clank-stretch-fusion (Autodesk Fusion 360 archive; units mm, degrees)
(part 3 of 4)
sketch "Profile" plane through (0, 0, 0) normal (1, 0, 0) x axis (0, 1, 0)
  line L1 (20, -33) -> (-20, -33)
  line L2 (20, 27) -> (20, -33)
  line L3 (-20, 27) -> (20, 27)
  line L4 (-20, -33) -> (-20, 27)
  line L5 (-55, -61.5) -> (-55, -1.5)
  line L6 (120, -61.5) -> (-55, -61.5)
  line L7 (120, -1.5) -> (120, -61.5)
  line L8 (20, -33) -> (-20, 27)
  line L9 (120, -1.5) -> (-55, -1.5)
  line L10 (106.0415, 5) -> (104.0207, 1.5)
  line L11 (104.0207, 8.5) -> (106.0415, 5)
  line L12 (99.9793, 8.5) -> (104.0207, 8.5)
  line L13 (97.9585, 5) -> (99.9793, 8.5)
  line L14 (99.9793, 1.5) -> (97.9585, 5)
  line L15 (104.0207, 1.5) -> (99.9793, 1.5)
  line L16 (97.9585, -67.85) -> (99.9793, -64.35)
  line L17 (104.0207, -71.35) -> (99.9793, -71.35)
  line L18 (106.0415, -67.85) -> (104.0207, -71.35)
  line L19 (99.9793, -71.35) -> (97.9585, -67.85)
  line L20 (104.0207, -64.35) -> (106.0415, -67.85)
  line L21 (99.9793, -64.35) -> (104.0207, -64.35)
  line L22 (-39.0415, 5) -> (-37.0207, 8.5)
  line L23 (-32.9793, 1.5) -> (-37.0207, 1.5)
  line L24 (-30.9585, 5) -> (-32.9793, 1.5)
  line L25 (-37.0207, 1.5) -> (-39.0415, 5)
  line L26 (-32.9793, 8.5) -> (-30.9585, 5)
  line L27 (-37.0207, 8.5) -> (-32.9793, 8.5)
  line L28 (-39.0415, -67.85) -> (-37.0207, -64.35)
  line L29 (-32.9793, -71.35) -> (-37.0207, -71.35)
  line L30 (-30.9585, -67.85) -> (-32.9793, -71.35)
  line L31 (-37.0207, -71.35) -> (-39.0415, -67.85)
  line L32 (-32.9793, -64.35) -> (-30.9585, -67.85)
  line L33 (-37.0207, -64.35) -> (-32.9793, -64.35)
  line L34 (-35, -67.85) -> (-35, 5)
  line L35 (102, -67.85) -> (102, 5)
  line L36 (10, 17) -> (-10, 17)
  line L37 (10, -23) -> (10, 17)
  line L38 (-10, -23) -> (10, -23)
  line L39 (-10, 17) -> (-10, -23)
  line L40 (10, 17) -> (-10, -23)
  line L41 (-23.9585, -58.31) -> (-28.9585, -58.31)
  line L42 (-23.9585, -72.31) -> (-23.9585, -58.31)
  line L43 (-28.9585, -72.31) -> (-23.9585, -72.31)
  line L44 (-28.9585, -58.31) -> (-28.9585, -72.31)
  line L45 (-42, -55.77) -> (-42, -74.85)
  line L46 (-23.9585, -55.77) -> (-42, -55.77)
  line L47 (-23.9585, -54.77) -> (-23.9585, -55.77)
  line L48 (-42, -54.77) -> (-23.9585, -54.77)
  line L49 (-42, 12) -> (-42, -54.77)
  line L50 (109, -74.85) -> (-42, -74.85)
  line L51 (109, -55.77) -> (109, -74.85)
  line L52 (90.9585, -55.77) -> (109, -55.77)
  line L53 (90.9585, -35.25) -> (90.9585, -55.77)
  line L54 (109, 12) -> (109, -35.25)
  line L55 (90.9585, -58.31) -> (95.9585, -58.31)
  line L56 (90.9585, -72.31) -> (90.9585, -58.31)
  line L57 (95.9585, -72.31) -> (90.9585, -72.31)
  line L58 (95.9585, -58.31) -> (95.9585, -72.31)
  line L59 (95, 12) -> (109, 12)
  line L60 (109, 0) -> (-42, 0)
  line L61 (-22.99, 12) -> (-42, 12)
  line L62 (-22.99, 0) -> (-22.99, 12)
  line L63 (109, -35.25) -> (90.9585, -35.25)
  line L64 (34, -0.85) -> (21, -0.85)
  line L65 (34, -5.85) -> (34, -0.85)
  line L66 (21, -5.85) -> (34, -5.85)
  line L67 (21, -0.85) -> (21, -5.85)
  line L68 (27.5, -5.85) -> (27.5, 0)
  line L69 (23.25, 18.5) -> (21.85, 18.5)
  line L70 (23.25, 8.5) -> (23.25, 18.5)
  line L71 (21.85, 8.5) -> (23.25, 8.5)
  line L72 (21.85, 18.5) -> (21.85, 8.5)
  line L73 (23, 8.5) -> (23, 18.5)
  line L74 (61.5, 8.85) -> (43.1, 8.85)
  line L75 (61.5, 22.35) -> (61.5, 8.85)
  line L76 (43.1, 22.35) -> (61.5, 22.35)
  line L77 (43.1, 8.85) -> (43.1, 22.35)
  line L78 (85.5, 22.35) -> (67.1, 22.35)
  line L79 (85.5, 8.85) -> (85.5, 22.35)
  line L80 (67.1, 8.85) -> (85.5, 8.85)
  line L81 (67.1, 22.35) -> (67.1, 8.85)
  line L82 (52.3, 8.85) -> (52.3, 22.35)
  line L83 (76.3, 8.85) -> (76.3, 22.35)
  line L84 (-22.74, 27.25) -> (-22.74, 0)
  line L85 (20.25, 27.25) -> (-20.25, 27.25)
  line L86 (20.25, -33.25) -> (20.25, 27.25)
  line L87 (-20.25, -33.25) -> (20.25, -33.25)
  line L88 (-20.25, 27.25) -> (-20.25, -33.25)
  line L89 (85.45, 30.7) -> (43.15, 30.7)
  line L90 (85.45, 100.7) -> (85.45, 30.7)
  line L91 (43.15, 100.7) -> (85.45, 100.7)
  line L92 (43.15, 30.7) -> (43.15, 100.7)
  line L93 (67.1, 15.6) -> (61.5, 15.6)
  line L94 (64.3, 30.7) -> (64.3, 15.6)
  line L95 (93.45, 30.7) -> (35.15, 30.7)
  line L96 (93.45, 23.2) -> (93.45, 30.7)
  line L97 (35.15, 23.2) -> (93.45, 23.2)
  line L98 (35.15, 30.7) -> (35.15, 23.2)
  line L99 (-42, 8) -> (109, 8)
  line L100 (95, 0) -> (95, 12)
  line L101 (0, 0) -> (0, -3)
  line L102 (23, 8.4) -> (23, 8.5)
  line L103 (20.35, 8.4) -> (23, 8.4)
  line L104 (20.35, 27.35) -> (20.35, 8.4)
  line L105 (18, 27.35) -> (20.35, 27.35)
  line L106 (18, 38.35) -> (18, 27.35)
  line L107 (23, 38.35) -> (18, 38.35)
  line L108 (23, 18.5) -> (23, 38.35)
  line L109 (31.15, 8.4) -> (23.15, 8.4)
  line L110 (31.15, 38.35) -> (31.15, 8.4)
  line L111 (23.15, 38.35) -> (31.15, 38.35)
  line L112 (23.15, 8.4) -> (23.15, 38.35)
  line L113 (20.35, 8.4) -> (5.15, 8.4)
  line L114 (5.15, 27.35) -> (5.15, 8.4)
  line L115 (5.15, 27.35) -> (18, 27.35)
  line L116 (5.15, 38.35) -> (5.15, 27.35)
  line L117 (18, 38.35) -> (5.15, 38.35)
  line L118 (1.15, 38.35) -> (5.15, 38.35)
  line L119 (1.15, 27.25) -> (1.15, 38.35)
  line L120 (18, 27.25) -> (18, 27.35)
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  point P11 (102, 5)
  point P18 (102, 5)
  point P26 (102, -67.85)
  point P27 (102, -67.85)
  point P35 (-35, 5)
  point P36 (-35, 5)
  point P44 (-35, -67.85)
  point P45 (-35, -67.85)
  point P46 (-35, 5)
  point P47 (-35, -67.85)
  point P48 (102, 5)
  point P25 (102, -67.85)
  point P49 (102, -67.85)
  point P50 (-10, 17)
  point P54 (-10, 17)
  point P51 (10, 17)
  point P55 (10, 17)
  point P53 (-10, -23)
  point P56 (-10, -23)
  point P52 (10, -23)
  point P57 (10, -23)
  point P63 (-42, -55.77)
  point P78 (-42, 0)
  point P59 (-23.9585, -58.31)
  point P64 (-23.9585, -55.77)
  point P74 (90.9585, -58.31)
  point P60 (-23.9585, -72.31)
  point P69 (109, -55.77)
  point P87 (27.5, 0)
  point P88 (27.5, -5.85)
  point P93 (23, 18.5)
  point P94 (23, 8.5)
  point P95 (23, 13.5)
  point P98 (61.5, 22.35)
  point P97 (61.5, 8.85)
  point P104 (52.3, 22.35)
  point P105 (52.3, 8.85)
  point P106 (76.3, 22.35)
  point P107 (76.3, 8.85)
  point P108 (76.3, 15.6)
  point P81 (-22.99, 0)
  point P109 (-22.74, 0)
  point P120 (61.5, 15.6)
  point P121 (67.1, 15.6)
  point P122 (64.3, 15.6)
  point P123 (64.3, 30.7)
  point P128 (109, 8)
  point P129 (-42, 8)
  point P79 (109, 0)
  point P131 (95, 0)
  point P117 (85.45, 30.7)
  point P1 (0, 0)
  point P134 (0, -3)
  point P135 (0, 0)
  point P142 (23, 18.5)
  point P141 (23, 38.35)
  point P136 (23, 8.4)
  point P137 (20.35, 8.4)
  point P148 (20.35, 8.4)
  point P149 (5.15, 27.35)
  point P150 (5.15, 27.35)
  point P140 (18, 38.35)
  point P152 (18, 38.35)
  point P155 (18, 27.25)
  point P154 (1.15, 27.25)
  point P156 (35, 0)
  point P158 (20.25, -9.85)
  point P164 (-42, -46.5)
  point P166 (38, 0)
  point P2 (-20, -33)
  point P5 (-20, 27)
  point P4 (20, 27)
  point P6 (-55, -1.5)
  point P7 (-55, -61.5)
  point P14 (104.0207, 8.5)
  point P8 (120, -61.5)
  point P10 (102, 5)
  point P20 (104.0207, -64.35)
  point P29 (-32.9793, 8.5)
  point P38 (-32.9793, -64.35)
  point P9 (120, -1.5)
  point P34 (-35, 5)
  point P43 (-35, -67.85)
  point P42 (-30.9585, -67.85)
  point P61 (-28.9585, -72.31)
  point P65 (-23.9585, -54.77)
  point P19 (97.9585, -67.85)
  point P85 (34, -5.85)
  point P86 (21, -5.85)
  point P84 (34, -0.85)
  point P83 (21, -0.85)
  point P90 (23.25, 18.5)
  point P91 (23.25, 8.5)
  point P89 (21.85, 18.5)
  point P96 (43.1, 8.85)
  point P99 (43.1, 22.35)
  point P80 (-22.99, 12)
  point P3 (20, -33)
  point P118 (85.45, 100.7)
  point P119 (43.15, 100.7)
  point P116 (43.15, 30.7)
  point P125 (93.45, 30.7)
  point P126 (93.45, 23.2)
  point P112 (20.25, 27.25)
  point P145 (31.15, 38.35)
  point P146 (23.15, 38.35)
  point P139 (18, 27.35)
  point P151 (5.15, 38.35)
  point P153 (1.15, 38.35)
  point P159 (43, -40)
  point P162 (43, -41)
  point P161 (81, -41)
  point P163 (62, -41)
  point P168 (87, -13)
  point P169 (87, -33)
  point P174 (107.25, -33.25)
  horizontal L1
  vertical L2
  horizontal L3
  vertical L4
  perpendicular L5 L6
  perpendicular L6 L7
  perpendicular L7 L9
  coincident P11 P18
  coincident P26 P27
  coincident P35 P36
  coincident P44 P45
  coincident P36 P46
  coincident P44 P47
  coincident P18 P48
  coincident P25 P49
  vertical L34
  horizontal L36
  vertical L37
  horizontal L38
  vertical L39
  coincident P50 P54
  coincident P51 P55
  coincident P53 P56
  coincident P52 P57
  horizontal L33
  horizontal L23
  horizontal L15
  horizontal L21
  horizontal L41
  vertical L42
  horizontal L43
  vertical L44
  perpendicular L6 L45
  perpendicular L45 L46
  perpendicular L46 L47
  perpendicular L34 L48
  perpendicular L48 L49
  perpendicular L45 L50
  perpendicular L6 L51
  perpendicular L51 L52
  perpendicular L6 L53
  horizontal L55
  vertical L56
  horizontal L57
  vertical L58
  perpendicular L54 L59
  horizontal L50
  coincident P63 L49
  coincident L49 P78
  perpendicular L2 L60
  perpendicular L49 L61
  perpendicular L61 L62
  coincident P59 L47
  equal L43 L57
  coincident P64 L52
  coincident L53 P74
  coincident P59 L55
  coincident P60 L57
  vertical L35
  coincident P69 L54
  vertical L54
  horizontal L63
  horizontal L64
  vertical L65
  horizontal L66
  vertical L67
  coincident L60 P87
  midpoint L66 P88
  perpendicular L66 L68
  horizontal L69
  vertical L70
  horizontal L71
  vertical L72
  coincident L69 P93
  coincident L71 P94
  perpendicular L71 L73
  midpoint L73 P95
  horizontal L74
  vertical L75
  horizontal L76
  vertical L77
  horizontal L78
  vertical L79
  horizontal L80
  vertical L81
  coincident P98 L78
  coincident P97 L80
  equal L76 L78
  midpoint L76 P104
  midpoint L74 P105
  midpoint L78 P106
  midpoint L80 P107
  midpoint L83 P108
  coincident L60 P81
  coincident L60 P109
  perpendicular L60 L84
  horizontal L85
  vertical L86
  horizontal L87
  vertical L88
  horizontal L89
  vertical L90
  horizontal L91
  vertical L92
  midpoint L75 P120
  midpoint L81 P121
  midpoint L93 P122
  midpoint L89 P123
  vertical L94
  horizontal L95
  vertical L96
  horizontal L97
  vertical L98
  coincident L54 P128
  coincident L49 P129
  perpendicular L49 L99
  coincident L54 P79
  coincident L60 P131
  perpendicular L60 L100
  coincident P117 L95
  midpoint L8 L40
  coincident P1 L60
  midpoint L40 P134
  coincident P1 P135
  vertical L101
  perpendicular L71 L102
  perpendicular L73 L103
  perpendicular L85 L104
  perpendicular L86 L105
  perpendicular L85 L106
  perpendicular L86 L107
  perpendicular L85 L108
  coincident P93 P142
  horizontal L109
  vertical L110
  horizontal L111
  vertical L112
  coincident P141 L111
  coincident P136 L109
  perpendicular L106 L113
  coincident P137 P148
  perpendicular L113 L114
  perpendicular L106 L115
  coincident P149 P150
  perpendicular L115 L116
  perpendicular L114 L117
  coincident P140 P152
  perpendicular L116 L118
  coincident L85 P155
  perpendicular L85 L120
  coincident L85 P154
  vertical L119
  coincident L60 P156
  coincident L86 P158
  coincident L49 P164
  coincident L60 P166
  dimension "d2020" distance P2 P5 = 60
  dimension "d2021" distance P4 P5 = 40
  dimension "d2022" distance P6 P7 = 60
  dimension "d2024" distance P14 L15 = 7 (= "hw_m4hex_d")
  dimension "d2025" diameter = 4.25
  dimension "d2026" diameter = 13 (= "od_bearings")
  dimension "d2028" distance P1 P8 = 120
  dimension "d2029" distance P1 P10 = 102
  dimension "d2030" distance P20 L17 = 7 (= "hw_m4hex_d")
  dimension "d2031" diameter = 4.25
  dimension "d2032" diameter = 13 (= "od_bearings")
  dimension "d2033" distance P29 L23 = 7 (= "hw_m4hex_d")
  dimension "d2034" diameter = 4.25
  dimension "d2035" diameter = 13 (= "od_bearings")
  dimension "d2036" distance P38 L29 = 7 (= "hw_m4hex_d")
  dimension "d2037" diameter = 4.25
  dimension "d2038" diameter = 13 (= "od_bearings")
  dimension "d2039" distance P9 P10 = 6.5 (= "od_bearings / 2")
  dimension "d2040" distance P6 P34 = 6.5 (= "od_bearings / 2")
  dimension "d2041" distance P7 P43 = 6.35 (= "od_bearings / 2 - preload")
  dimension "d2042" distance P8 P25 = 6.35 (= "od_bearings / 2 - preload")
  dimension "d2046" distance P50 P51 = 20 (= "40 mm - 20 mm")
  dimension "d2047" distance P50 P53 = 40
  dimension "d2048" diameter = 5.5
  dimension "d2049" distance P7 P43 = 20
  dimension "d2050" distance P1 P34 = 35
  dimension "d2051" distance P43 L45 = 7 (= "od_bearings / 2 + 0.5 mm")
  dimension "d2052" distance P43 L50 = 7 (= "d2051")
  dimension "d2053" distance P42 L44 = 2
  dimension "d2055" distance L43 L50 = 2.54 (= "flex_t")
  dimension "d2056" distance P60 P61 = 5 (= "flex_l")
  dimension "d2057" distance L41 L46 = 2.54 (= "flex_t")
  dimension "d2058" distance P64 P65 = 1
  dimension "d2059" distance P5 P6 = 28.5 (= "21.5 mm + 7 mm")
  dimension "d2060" distance P6 L60 = 1.5
  dimension "d2061" distance P34 L61 = 7 (= "od_bearings / 2 + 0.5 mm")
  dimension "d2062" distance P59 P60 = 14
  dimension "d2063" distance P19 L58 = 2 (= "d2053")
  dimension "d2064" distance P25 L51 = 7 (= "od_bearings / 2 + 0.5 mm")
  dimension "d2066" distance P85 P86 = 13 (= "od_bearings")
  dimension "d2067" distance P84 P85 = 5 (= "t_bearings")
  dimension "d2068" distance L60 L64 = 0.85 (= "t_m4_washer")
  dimension "d2069" distance L2 P83 = 1
  dimension "d2070" distance P90 P91 = 10
  dimension "d2073" distance P90 P93 = 0.25 (= "belt_pdo_backside")
  dimension "d2074" distance P89 P93 = 1.15 (= "belt_pdo_toothside")
  dimension "d2075" distance L3 P95 = 13.5
  dimension "d2076" distance P96 P99 = 13.5
  dimension "d2077" distance P98 P99 = 18.4
  dimension "d2078" distance P9 P108 = 17.1
  dimension "d2082" distance P80 L84 = 0.25
  dimension "d2084" distance P2 L87 = 0.25
  dimension "d2085" distance L4 L88 = 0.25
  dimension "d2086" distance P3 L86 = 0.25 (= "d2085")
  dimension "d2087" distance L3 L85 = 0.25
  dimension "d2088" distance L84 L88 = 2.49
  dimension "d2091" diameter = 11
  dimension "d2094" distance P118 P119 = 42.3
  dimension "d2095" distance P116 P119 = 70
  dimension "d2096" distance P104 L97 = 0.85 (= "t_m4_washer")
  dimension "d2097" distance P10 L59 = 7 (= "od_bearings / 2 + 0.5 mm")
  dimension "d2098" distance P91 L99 = 0.5
  dimension "d2099" distance L2 P95 = 3
  dimension "d2110" distance P125 P126 = 7.5
  dimension "d2111" distance P116 L98 = 8
  dimension "d2112" distance P117 L96 = 8
  dimension "d2113" distance P105 P107 = 24
  dimension "d2117" distance P94 P136 = 0.1
  dimension "d2118" distance P136 L112 = 0.15
  dimension "d2119" distance P112 L104 = 0.1
  dimension "d2120" distance P145 P146 = 8
  dimension "d2121" distance P112 L105 = 0.1
  dimension "d2122" distance P139 P140 = 11
  dimension "d2123" distance P140 P145 = 13.15
  dimension "d2124" distance P140 P141 = 5
  dimension "d2163" distance P145 P151 = 26
  dimension "d2174" distance P145 P153 = 30
  dimension "d2206" distance = 4
  dimension "d2207" distance = 1
  dimension "d2242" distance L98 P145 = 4
  dimension "d2243" distance P10 L100 = 7 (= "od_bearings / 2 + 0.5 mm")
  dimension "d2277" distance L60 P125 = 30.7
  dimension "d2348" distance L80 L99 = 0.85 (= "t_m4_washer")
  dimension "d2401" distance P159 P162 = 1
  dimension "d2402" distance P161 P162 = 38
  dimension "d2403" distance P1 P163 = 62
  dimension "d2404" distance = 13.5
  dimension "d2406" distance = 18
  dimension "d2409" distance P168 P169 = 20
  dimension "d2410" distance = 6
  dimension "d2411" diameter = 5.5
  dimension "d2413" distance = 0.25
  dimension "d2414" distance = 8
  dimension "d2415" distance L63 P174 = 2
  dimension "d2423" distance = 67
  dimension "d2424" distance P134 P163 = 38
  dimension "d523" OffsetX = 0
  dimension "d524" OffsetY = 0
  dimension "d525" OffsetZ = 0
  dimension "d526" AngleZ = 0
  dimension "d567" OffsetX = 0
  dimension "d568" OffsetY = 0
  dimension "d569" OffsetZ = 0
  dimension "d570" AngleZ = 0
extrude "Extrude138" new body sketch "Profile" blind 9 from offset 1.5
extrude "Extrude139" sketch "Profile" to an object offset -3
extrude "Extrude140" sketch "Profile" to an object from offset 2.5
chamfer "Chamfer23" distance 3
extrude "Extrude142" sketch "Profile" profile of L73 L102 L103 L104 L105 L106 L107 L108 L109 L110 L111 L112 blind -28 bodies "YL Belt Clip Teeth", "YL Belt Clip Face"
extrude "Extrude143" sketch "Profile" blind 10
sketch "Belt Clip" plane through (0, 5.15, 0) normal (0, -1, 0) x axis (1, 0, 0)
  line L1 (-17.5, 8.4) -> (-17.5, 38.35)
  line L2 (-7.5, 38.35) -> (-7.5, 8.4)
  line L3 (-17.5, 38.35) -> (-7.5, 38.35)
  line L4 (-12.5, 29.5415) -> (-9, 27.5207)
  line L5 (-16, 27.5207) -> (-12.5, 29.5415)
  line L6 (-16, 23.4793) -> (-16, 27.5207)
  line L7 (-12.5, 21.4585) -> (-16, 23.4793)
  line L8 (-9, 23.4793) -> (-12.5, 21.4585)
  line L9 (-9, 27.5207) -> (-9, 23.4793)
  line L10 (-12.5, 25.5) -> (-12.5, 38.35)
  line L11 (-7.5, 18.5) -> (-17.5, 18.5)
  line L12 (-7.5, 8.4) -> (-17.5, 8.4)
  circle C1 centre (-12.5, 25.5) radius 2.125
  point P6 (-12.5, 25.5)
  point P13 (-12.5, 25.5)
  point P14 (-12.5, 38.35)
  point P15 (-12.5, 25.5)
  point P17 (-17.5, 18.5)
  point P18 (-7.5, 18.5)
  point P7 (-9, 27.5207)
  point P16 (0, 13.5)
  coincident P6 P13
  midpoint L3 P14
  coincident P13 P15
  vertical L10
  coincident L1 P17
  coincident L2 P18
  perpendicular L2 L11
  vertical L6
  dimension "d2132" distance P7 L6 = 7 (= "hw_m4hex_d")
  dimension "d2133" diameter C1 = 4.25
  dimension "d2134" distance P13 P16 = 12
  dimension "d2135" distance P16 L11 = 5
extrude "Extrude144" cut sketch "Belt Clip" profile of C1 to an object
extrude "Extrude145" cut sketch "Belt Clip" profile of C1 L4 L5 L6 L7 L8 L9 against normal blind 6
chamfer "Chamfer24" distance 2.25
sketch "Belt Profile" plane through (0, 0, 8.4) normal (0, 0, -1) x axis (1, 0, 0)
  line L1 (10.5, -20.35) -> (10.5, -23)
  line L2 (-7.5, -20.35) -> (10.5, -20.35)
  line L3 (-7.5, -5.15) -> (-7.5, -20.35)
  line L4 (-17.5, -23) -> (-17.5, -5.15)
  line L5 (10.5, -23) -> (-17.5, -23)
  line L6 (9.5, -20.35) -> (9.5, -23)
  line L7 (10.5, -21.85) -> (0, -21.85)
  line L8 (9.5, -22.6) -> (10.5, -22.6)
  line L9 (-17.5, -5.15) -> (-7.5, -5.15)
  arc A1 centre (9.5, -22.4) radius 0.55 clockwise from (9.5, -21.85) to (9.9889, -22.148)
  arc A2 centre (10.2393, -22.45) radius 0.15 clockwise from (10.2393, -22.6) to (10.0907, -22.4704)
  arc A3 centre (9.1, -22.6062) radius 1 clockwise from (9.9889, -22.148) to (10.0907, -22.4704)
  point P8 (9.5, -23)
  point P9 (9.5, -20.35)
  point P10 (0, -21.85)
  point P11 (0, -21.85)
  point P12 (10.5, -21.85)
  point P13 (10.5, -22.6)
  point P14 (9.5, -22.6)
  point P17 (9.5, -21.85)
  point P15 (9.5, -22.4)
  point P20 (10.2393, -22.6)
  point P19 (10.0907, -22.4704)
  point P22 (10.0907, -22.4704)
  point P3 (10.5, -20.35)
  point P21 (9.1, -22.6062)
  coincident L5 P8
  coincident L2 P9
  perpendicular L2 L6
  coincident P10 P11
  coincident L1 P12
  perpendicular L1 L7
  coincident L1 P13
  coincident L6 P14
  perpendicular L6 L8
  coincident L6 P17
  coincident L7 P17
  coincident L6 P15
  coincident L8 P20
  tangent A1 A3
  coincident P19 P22
  tangent L8 A2
  tangent A2 A3
  dimension "d2141" distance P3 L6 = 1
  dimension "d2142" distance P12 L8 = 0.75
  dimension "d2143" radius A1 = 0.55
  dimension "d2144" radius A2 = 0.15
  dimension "d2146" radius A3 = 1
  dimension "d2147" distance L6 P21 = 0.4
extrude "Extrude146" new body sketch "Belt Profile" profile of L1 L5 L6 L8 A1 A2 A3 to an object offset -0.5
mirror "Mirror6" mirrorStitchTolerance 0.1
rectangular_pattern "R-Pattern2" countU 14 uSpaceDistance -2 vSpaceDistance 0
combine "Combine22"
sketch "Belt Slots" plane through (0, 18, 0) normal (0, -1, 0) x axis (1, 0, 0)
  line L1 (-7.5, 27.35) -> (-7.5, 38.35)
  line L2 (10.5, 27.35) -> (-7.5, 27.35)
  line L3 (10.5, 38.35) -> (10.5, 27.35)
  line L4 (-7.5, 38.35) -> (10.5, 38.35)
  line L5 (4.5, 27.8085) -> (1, 29.8293)
  line L6 (8, 29.8293) -> (4.5, 27.8085)
  line L7 (8, 33.8707) -> (8, 29.8293)
  line L8 (4.5, 35.8915) -> (8, 33.8707)
  line L9 (1, 33.8707) -> (4.5, 35.8915)
  line L10 (1, 29.8293) -> (1, 33.8707)
  line L11 (-0.5, 34.1) -> (4.5, 34.1)
  line L12 (4.5, 29.6) -> (-0.5, 29.6)
  line L13 (-0.5, 31.85) -> (4.5, 31.85)
  line L14 (-2.75, 34.1) -> (-2.75, 31.85)
  line L15 (-0.5, 34.1) -> (-2.75, 34.1)
  line L16 (6.75, 34.1) -> (4.5, 34.1)
  line L17 (6.75, 31.85) -> (6.75, 34.1)
  circle C1 centre (4.5, 31.85) radius 2.125
  arc A1 centre (-0.5, 31.85) radius 2.25 clockwise from (-0.5, 29.6) to (-0.5, 34.1)
  arc A2 centre (4.5, 31.85) radius 2.25 clockwise from (4.5, 34.1) to (4.5, 29.6)
  point P13 (4.5, 31.85)
  point P14 (4.5, 31.85)
  point P19 (4.5, 31.85)
  point P21 (-2.75, 31.85)
  point P24 (6.75, 31.85)
  point P6 (-7.5, 31.85)
  point P10 (8, 33.8707)
  point P12 (1, 33.8707)
  point P20 (-0.5, 31.85)
  vertical L10
  coincident P13 P14
  tangent L11 A1
  tangent A1 L12
  parallel L11 L12
  tangent L12 A2
  tangent L11 A2
  perpendicular L10 L13
  coincident P14 P19
  midpoint A1 P21
  tangent A1 L14
  parallel L10 L14
  tangent A1 L15
  tangent A2 L16
  midpoint A2 P24
  tangent A2 L17
  dimension "d2159" distance P6 P13 = 12
  dimension "d2165" distance P10 P12 = 7 (= "d2164")
  dimension "d2171" distance L3 P13 = 6
  dimension "d2494" distance L2 P6 = 4.5
  dimension "d2495" distance P19 P20 = 5
  dimension "d2496" radius A1 = 2.25 (= "( 4.5 / 2 ) * 1 mm")
  dimension "d2497" diameter C1 = 4.25
extrude "Extrude147" cut sketch "Belt Slots" profile of C1 to an object
extrude "Extrude148" sketch "Belt Slots" profile of L5 L6 L7 L8 L9 L10 C1 to an object from offset -2
extrude "Extrude149" sketch "Profile" to an object offset 0.25
extrude "Extrude151" sketch "Profile" to an object
extrude "Extrude152" sketch "Profile" to an object
extrude "Extrude153" cut of existing geometry blind -0.2
extrude "Extrude154" cut sketch "Belt Slots" profile of L5 L9 L10 C1 L11 A1 L12 A2 L14 L15 L16 L17 to an object
extrude "Extrude155" sketch "Profile" to an object
offset_faces "OffsetFaces10" distance -0.25
combine "Combine23"
chamfer "Chamfer25" distance 2.75 (= "( ( 11 - 5.5 ) / 2 ) * 1 mm")
chamfer "Chamfer26" distance 3
sketch "Nugget Extend" plane through (-7.25, 0, 0) normal (-1, 0, 0) x axis (0, -1, 0)
  line L1 (-1.15, 27.25) -> (-4.9, 27.25)
  line L2 (-1.15, 38.35) -> (-1.15, 27.25)
  line L3 (-17.8, 38.35) -> (-1.15, 38.35)
  line L4 (-17.8, 27.25) -> (-17.8, 38.35)
  line L5 (-20.25, 27.25) -> (-17.8, 27.25)
  line L6 (-20.25, 8.4) -> (-20.25, 27.25)
  line L7 (-5.15, 8.4) -> (-20.25, 8.4)
  line L8 (-5.15, 14.4063) -> (-5.15, 8.4)
  line L9 (-4.9, 27.25) -> (-4.9, 19.0591)
  line L10 (-4.9, 38.35) -> (-4.9, 27.25)
  arc A1 centre (-10, 17) radius 5.5 clockwise from (-5.15, 14.4063) to (-4.9, 19.0591)
  point P2 (-4.9, 27.25)
  point P13 (-4.9, 27.25)
  point P14 (-4.9, 38.35)
  coincident P2 P13
  coincident L3 P14
  perpendicular L3 L10
extrude "Extrude176" add sketch "Nugget Extend" profile of L1 L2 L3 L10 to an object
sketch "Belt Tensioner" plane through (-17.5, 0, 0) normal (-1, 0, 0) x axis (0, -1, 0)
  line L1 (-22.6, 19) -> (-23, 19)
  line L2 (-5.15, 8.4) -> (-22.6, 8.4)
  line L3 (-5.15, 38.35) -> (-5.15, 8.4)
  line L4 (-23, 38.35) -> (-5.15, 38.35)
  line L5 (-23, 19) -> (-23, 38.35)
  line L6 (-13, 12.9585) -> (-16.5, 14.9793)
  line L7 (-9.5, 14.9793) -> (-13, 12.9585)
  line L8 (-9.5, 19.0207) -> (-9.5, 14.9793)
  line L9 (-13, 21.0415) -> (-9.5, 19.0207)
  line L10 (-16.5, 19.0207) -> (-13, 21.0415)
  line L11 (-16.5, 14.9793) -> (-16.5, 19.0207)
  line L12 (-10, 17) -> (10, 17)
  line L13 (-22.6, 8.4) -> (-22.6, 19)
  circle C1 centre (-13, 17) radius 2.25
  point P8 (-13, 17)
  point P15 (-13, 17)
  point P12 (-9.5, 19.0207)
  point P16 (-10, 17)
  coincident P8 P15
  vertical L8
  coincident P15 L12
  dimension "d2486" distance P12 L11 = 7 (= "hw_m4hex_d")
  dimension "d2487" diameter C1 = 4.5
  dimension "d2488" distance P8 P16 = 3
extrude "Extrude177" cut sketch "Belt Tensioner" profile of C1 to an object
extrude "Extrude178" sketch "Belt Tensioner" profile of C1 L6 L7 L8 L9 L10 L11 blind 5
extrude "Extrude156" cut sketch "Profile" to an object
sketch "Top Plate" plane through (0, 0, 0) normal (0, 0, 1) x axis (1, 0, 0)
  line L1 (0, 52.3) -> (-21.55, 52.3)
  line L2 (0, 76.3) -> (-21.55, 76.3)
  line L3 (-17.5, 20.25) -> (-17.5, -22.74)
  line L4 (-21.5, 20.25) -> (-21.5, -22.74)
  line L5 (-21.55, 76.3) -> (-21.55, 52.3)
  line L6 (-31.15, 52.3) -> (-29.75, 52.3)
  line L7 (-31.15, -45.1874) -> (-31.15, 52.3)
  line L8 (-29.75, -45.1874) -> (-31.15, -45.1874)
  line L9 (-29.75, 52.3) -> (-29.75, -45.1874)
  line L10 (-30, -45.1874) -> (-30, 52.3)
  line L11 (-26.35, 27.5) -> (0, 27.5)
  line L12 (-30.3915, 27.5) -> (-28.3707, 31)
  line L13 (-28.3707, 24) -> (-30.3915, 27.5)
  line L14 (-24.3293, 24) -> (-28.3707, 24)
  line L15 (-22.3085, 27.5) -> (-24.3293, 24)
  line L16 (-24.3293, 31) -> (-22.3085, 27.5)
  line L17 (-28.3707, 31) -> (-24.3293, 31)
  line L18 (2.4585, 27.5) -> (4.4793, 31)
  line L19 (4.4793, 24) -> (2.4585, 27.5)
  line L20 (8.5207, 24) -> (4.4793, 24)
  line L21 (10.5415, 27.5) -> (8.5207, 24)
  line L22 (8.5207, 31) -> (10.5415, 27.5)
  line L23 (4.4793, 31) -> (8.5207, 31)
  line L24 (-14.89, 32.67) -> (-30.81, 32.67)
  line L25 (-14.89, 37.67) -> (-14.89, 32.67)
  line L26 (-30.81, 37.67) -> (-14.89, 37.67)
  line L27 (-30.81, 32.67) -> (-30.81, 37.67)
  line L28 (-12.35, 21.25) -> (-33.35, 21.25)
  line L29 (-12.35, 37.67) -> (-12.35, 21.25)
  line L30 (-11.35, 37.67) -> (-12.35, 37.67)
  line L31 (-11.35, 20.25) -> (-11.35, 37.67)
  line L32 (-17.5, 20.25) -> (-11.35, 20.25)
  line L33 (-33.35, 42.65) -> (-33.35, 21.25)
  line L34 (-20.5, -22.74) -> (-17.5, -22.74)
  line L35 (-20.5, -42) -> (-20.5, -22.74)
  line L36 (-5.2, -42) -> (-20.5, -42)
  line L37 (-5.2, -28) -> (-5.2, -42)
  line L38 (1.35, -28) -> (-5.2, -28)
  line L39 (10.5, -42) -> (1.5, -42)
  line L40 (1.35, -22.74) -> (-20.5, -22.74)
  line L41 (1.35, -28) -> (1.35, -22.74)
  line L42 (-5.2, 94.85) -> (-5.2, 109)
  line L43 (13.5, 94.85) -> (-5.2, 94.85)
  line L44 (13.5, 20.25) -> (13.5, 94.85)
  line L45 (-20.5, 109) -> (-5.2, 109)
  line L46 (-20.5, 85.45) -> (-20.5, 109)
  line L47 (0, 93.45) -> (0, 35.15)
  line L48 (7.5, 20.25) -> (13.5, 20.25)
  line L49 (10.5, -22.74) -> (10.5, -20.25)
  line L50 (-17.5, -22.74) -> (10.5, -22.74)
  line L51 (7.5, 20.25) -> (-17.5, 20.25)
  line L52 (-14.7, 85.45) -> (27.6, 85.45)
  line L53 (-14.7, 43.15) -> (-14.7, 85.45)
  line L54 (27.6, 43.15) -> (-14.7, 43.15)
  line L55 (27.6, 85.45) -> (27.6, 43.15)
  line L56 (-14.7, 43.15) -> (27.6, 85.45)
  line L57 (-9.05, 79.8) -> (21.95, 79.8)
  line L58 (-9.05, 48.8) -> (-9.05, 79.8)
  line L59 (21.95, 48.8) -> (-9.05, 48.8)
  line L60 (21.95, 79.8) -> (21.95, 48.8)
  line L61 (27.6, 43.15) -> (-14.7, 85.45)
  line L62 (6.45, 64.3) -> (0, 64.3)
  line L63 (-17.5085, 52.3) -> (-19.5293, 48.8)
  line L64 (-19.5293, 55.8) -> (-17.5085, 52.3)
  line L65 (-23.5707, 55.8) -> (-19.5293, 55.8)
  line L66 (-25.5915, 52.3) -> (-23.5707, 55.8)
  line L67 (-23.5707, 48.8) -> (-25.5915, 52.3)
  line L68 (-19.5293, 48.8) -> (-23.5707, 48.8)
  line L69 (-19.5293, 72.8) -> (-23.5707, 72.8)
  line L70 (-23.5707, 79.8) -> (-19.5293, 79.8)
  line L71 (-19.5293, 79.8) -> (-17.5085, 76.3)
  line L72 (-17.5085, 76.3) -> (-19.5293, 72.8)
  line L73 (-23.5707, 72.8) -> (-25.5915, 76.3)
  line L74 (-25.5915, 76.3) -> (-23.5707, 79.8)
  line L75 (-26.3293, 60.8) -> (-30.3707, 60.8)
  line L76 (-30.3707, 67.8) -> (-26.3293, 67.8)
  line L77 (-26.3293, 67.8) -> (-24.3085, 64.3)
  line L78 (-24.3085, 64.3) -> (-26.3293, 60.8)
  line L79 (-30.3707, 60.8) -> (-32.3915, 64.3)
  line L80 (-32.3915, 64.3) -> (-30.3707, 67.8)
  line L81 (-3.3293, 34.65) -> (-7.3707, 34.65)
  line L82 (-7.3707, 41.65) -> (-3.3293, 41.65)
  line L83 (-3.3293, 41.65) -> (-1.3085, 38.15)
  line L84 (-1.3085, 38.15) -> (-3.3293, 34.65)
  line L85 (-7.3707, 34.65) -> (-9.3915, 38.15)
  line L86 (-9.3915, 38.15) -> (-7.3707, 41.65)
  line L87 (-12.4793, 86.95) -> (-16.5207, 86.95)
  line L88 (-16.5207, 93.95) -> (-12.4793, 93.95)
  line L89 (-12.4793, 93.95) -> (-10.4585, 90.45)
  line L90 (-10.4585, 90.45) -> (-12.4793, 86.95)
  line L91 (-16.5207, 86.95) -> (-18.5415, 90.45)
  line L92 (-18.5415, 90.45) -> (-16.5207, 93.95)
  line L93 (20.1207, 86.95) -> (16.0793, 86.95)
  line L94 (16.0793, 93.95) -> (20.1207, 93.95)
  line L95 (20.1207, 93.95) -> (22.1415, 90.45)
  line L96 (22.1415, 90.45) -> (20.1207, 86.95)
  line L97 (16.0793, 86.95) -> (14.0585, 90.45)
  line L98 (14.0585, 90.45) -> (16.0793, 93.95)
  line L99 (-14.5, 90.45) -> (18.1, 90.45)
  line L100 (-28.35, 64.3) -> (-21.55, 64.3)
  line L101 (-15.7, 85.45) -> (-15.7, 42.65)
  line L102 (-33.35, 85.45) -> (-15.7, 85.45)
  line L103 (-33.35, 42.65) -> (-33.35, 85.45)
  line L104 (-15.2, 85.95) -> (-15.2, 42.65)
  line L105 (-20.5, 85.95) -> (-15.2, 85.95)
  line L106 (-5.2, 94.85) -> (-20.5, 94.85)
  line L107 (-11.35, 42.65) -> (-15.2, 42.65)
  line L108 (-11.35, 37.67) -> (-11.35, 42.65)
  line L109 (13.5, 33.65) -> (-11.35, 33.65)
  line L110 (-33.35, 42.65) -> (-15.7, 42.65)
  line L111 (28.1, 20.25) -> (13.5, 20.25)
  line L112 (28.1, 94.85) -> (28.1, 20.25)
  line L113 (13.5, 94.85) -> (28.1, 94.85)
  line L114 (28.1, 33.65) -> (13.5, 33.65)
  line L115 (28.1, 20) -> (28.1, 20.25)
  line L116 (23.1, 20) -> (28.1, 20)
  line L117 (22.85, 20.25) -> (23.1, 20)
  line L118 (28.1, 42.65) -> (-11.35, 42.65)
  line L119 (28.1, 85.95) -> (-15.2, 85.95)
  line L120 (-21.55, 66.1) -> (-21.55, 62.5)
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  point P2 (-21.55, 52.3)
  point P7 (-21.55, 52.3)
  point P4 (0, 52.3)
  point P8 (0, 52.3)
  point P3 (-21.55, 76.3)
  point P9 (-21.55, 76.3)
  point P5 (0, 76.3)
  point P10 (0, 76.3)
  point P11 (-17.5, -22.74)
  point P13 (-21.5, -22.74)
  point P12 (-17.5, 20.25)
  point P14 (-21.5, 20.25)
  point P15 (-21.55, 52.3)
  point P17 (-21.55, 52.3)
  point P18 (-21.55, 76.3)
  point P23 (-30, 52.3)
  point P24 (-30, -45.1874)
  point P27 (0, 27.5)
  point P28 (0, 27.5)
  point P25 (-26.35, 27.5)
  point P29 (-26.35, 27.5)
  point P26 (6.5, 27.5)
  point P30 (-26.35, 27.5)
  point P38 (-26.35, 27.5)
  point P31 (6.5, 27.5)
  point P45 (6.5, 27.5)
  point P48 (-14.89, 37.67)
  point P56 (-17.5, 20.25)
  point P57 (-17.5, -22.74)
  point P60 (-5.2, -42)
  point P62 (1.35, -28)
  point P67 (1.35, -28)
  point P61 (-5.2, -28)
  point P58 (-20.5, -22.74)
  point P78 (7.5, 20.25)
  point P83 (7.5, 20.25)
  point P88 (6.45, 64.3)
  point P91 (-9.05, 48.8)
  point P89 (21.95, 79.8)
  point P92 (21.95, 48.8)
  point P6 (0, 64.3)
  point P93 (0, 64.3)
  point P94 (6.45, 64.3)
  point P95 (21.95, 79.8)
  point P96 (21.95, 48.8)
  point P90 (-9.05, 79.8)
  point P97 (-9.05, 79.8)
  point P98 (-9.05, 48.8)
  point P100 (-21.55, 52.3)
  point P107 (-21.55, 52.3)
  point P108 (-21.55, 76.3)
  point P115 (-21.55, 76.3)
  point P16 (-21.55, 76.3)
  point P116 (-28.35, 64.3)
  point P123 (-28.35, 64.3)
  point P124 (-5.35, 38.15)
  point P131 (-5.35, 38.15)
  point P132 (-14.5, 90.45)
  point P139 (-14.5, 90.45)
  point P140 (18.1, 90.45)
  point P147 (18.1, 90.45)
  point P148 (18.1, 90.45)
  point P149 (-14.5, 90.45)
  point P150 (-21.55, 64.3)
  point P151 (-28.35, 64.3)
  point P70 (-5.2, 94.85)
  point P159 (-5.2, 94.85)
  point P53 (-11.35, 37.67)
  point P161 (-11.35, 37.67)
  point P162 (-11.35, 33.65)
  point P163 (13.5, 33.65)
  point P156 (-15.2, 42.65)
  point P85 (-14.7, 85.45)
  point P71 (13.5, 94.85)
  point P166 (13.5, 94.85)
  point P167 (28.1, 33.65)
  point P170 (22.85, 20.25)
  point P171 (28.1, 42.65)
  point P172 (28.1, 85.95)
  point P173 (-21.55, 76.3)
  point P177 (-21.55, 62.5)
  point P176 (-21.55, 52.3)
  point P179 (-33.35, 57.3)
  point P180 (-33.35, 71.3)
  point P181 (-15.7, 66.1)
  point P182 (-15.7, 62.5)
  point P74 (-20.5, 85.45)
  point P55 (-33.35, 42.65)
  point P152 (-33.35, 42.65)
  point P184 (18.1, 38.15)
  point P191 (18.1, 38.15)
  point P192 (18.1, 90.45)
  point P193 (18.1, 38.15)
  point P194 (18.1, 38.15)
  point P195 (-5.35, 38.15)
  point P158 (-20.5, 94.85)
  point P183 (-20.5, 85.95)
  point P196 (6, 46.65)
  point P203 (6, 46.65)
  point P206 (6, 46.65)
  point P216 (28.1, 59.3)
  point P218 (28.1, 69.3)
  point P19 (-29.75, 52.3)
  point P20 (-31.15, 52.3)
  point P1 (0, 0)
  point P39 (4.4793, 31)
  point P42 (8.5207, 24)
  point P32 (-28.3707, 31)
  point P46 (-30.81, 32.67)
  point P49 (-30.81, 37.67)
  point P52 (-12.35, 37.67)
  point P63 (0, -35)
  point P64 (1.5, -42)
  point P59 (-20.5, -42)
  point P65 (10.5, -42)
  point P68 (0, 95)
  point P77 (0, 102)
  point P84 (27.6, 85.45)
  point P87 (27.6, 43.15)
  point P104 (-23.5707, 55.8)
  point P112 (-23.5707, 79.8)
  point P120 (-30.3707, 67.8)
  point P128 (-7.3707, 41.65)
  point P136 (-16.5207, 93.95)
  point P144 (16.0793, 93.95)
  point P86 (-14.7, 43.15)
  point P168 (28.1, 20)
  point P169 (23.1, 20)
  point P154 (-15.7, 85.45)
  coincident P2 P7
  coincident P4 P8
  coincident P3 P9
  coincident P5 P10
  horizontal L1
  horizontal L2
  vertical L4
  horizontal P11 P13
  horizontal P12 P14
  coincident P15 P17
  coincident P3 P18
  vertical L5
  horizontal L6
  vertical L7
  horizontal L8
  vertical L9
  coincident P15 L6
  coincident L6 P23
  coincident L8 P24
  perpendicular L8 L10
  coincident P27 P28
  perpendicular L7 L11
  coincident P25 P29
  coincident P26 L11
  coincident P30 P38
  coincident P31 P45
  horizontal L23
  horizontal L17
  horizontal L24
  vertical L25
  horizontal L26
  vertical L27
  perpendicular L9 L28
  perpendicular L28 L29
  perpendicular L28 L31
  perpendicular L7 L32
  horizontal L30
  coincident P48 L30
  perpendicular L28 L33
  coincident P12 L32
  coincident P12 P56
  coincident P11 P57
  perpendicular L7 L34
  perpendicular L34 L35
  perpendicular L35 L36
  perpendicular L36 L37
  perpendicular L37 L38
  coincident P60 L39
  perpendicular L35 L40
  perpendicular L40 L41
  coincident P62 P67
  vertical L42
  perpendicular L42 L43
  perpendicular L43 L44
  perpendicular L42 L45
  perpendicular L45 L46
  coincident P61 L42
  coincident P58 L46
  perpendicular L44 L48
  coincident P78 P83
  horizontal L52
  vertical L53
  horizontal L54
  vertical L55
  equal L52 L53
  midpoint L56 P88
  horizontal L57
  vertical L58
  horizontal L59
  vertical L60
  coincident L56 P91
  coincident L56 P89
  coincident P92 L61
  coincident P6 P93
  coincident P88 P94
  horizontal L62
  coincident P89 P95
  coincident P92 P96
  coincident P90 P97
  coincident P91 P98
  coincident P100 P107
  horizontal L65
  coincident P108 P115
  horizontal L70
  coincident P16 P108
  coincident P15 P107
  coincident P116 P123
  horizontal L76
  coincident P124 P131
  horizontal L82
  coincident P132 P139
  horizontal L88
  coincident P140 P147
  horizontal L94
  coincident P147 P148
  coincident P139 P149
  horizontal L99
  midpoint L5 P150
  coincident P123 P151
  horizontal L100
  vertical L101
  horizontal L102
  vertical L103
  perpendicular L87 L104
  perpendicular L104 L105
  coincident P70 P159
  perpendicular L104 L107
  perpendicular L107 L108
  coincident P53 P161
  coincident L31 P162
  coincident L44 P163
  perpendicular L44 L109
  horizontal L110
  coincident P156 L110
  coincident P85 L102
  perpendicular L44 L111
  perpendicular L48 L112
  perpendicular L44 L113
  coincident P71 P166
  coincident L112 P167
  perpendicular L112 L114
  perpendicular L111 L115
  perpendicular L112 L116
  coincident L111 P170
  coincident L112 P171
  perpendicular L112 L118
  coincident L112 P172
  perpendicular L112 L119
  coincident P115 P173
  coincident L5 P177
  coincident P107 P176
  perpendicular L100 L120
  coincident L103 P179
  coincident L103 P180
  coincident L101 P181
  coincident L101 P182
  coincident P74 L102
  coincident P55 P152
  coincident P184 P191
  coincident P147 P192
  coincident P191 P193
  coincident P184 P194
  coincident P124 P195
  coincident L46 P158
  coincident L46 P183
  horizontal L106
  coincident P196 P203
  coincident P196 P206
  coincident L112 P216
  coincident L112 P218
  dimension "d2197" distance L3 L4 = 4
  dimension "d2198" diameter = 16.4
  dimension "d2199" diameter = 18.4
  dimension "d2200" distance P19 P23 = 0.25 (= "belt_pdo_backside")
  dimension "d2201" distance P20 P23 = 1.15 (= "belt_pdo_toothside")
  dimension "d2202" distance P1 P24 = 30
  dimension "d2203" diameter = 13 (= "od_bearings")
  dimension "d2204" distance P1 P26 = 6.5 (= "od_bearings / 2")
  dimension "d2205" distance P1 P25 = 26.35 (= "20 mm + od_bearings / 2 - preload")
  dimension "d2210" diameter = 4.25
  dimension "d2211" distance P39 P42 = 7 (= "hw_m4hex_d")
  dimension "d2212" distance P32 L14 = 7 (= "hw_m4hex_d")
  dimension "d2213" distance L17 L24 = 1.67
  dimension "d2214" distance P46 P49 = 5 (= "flex_l")
  dimension "d2215" distance L25 L29 = 2.54 (= "flex_t")
  dimension "d2216" distance L27 L33 = 2.54 (= "flex_t")
  dimension "d2217" distance P25 L33 = 7 (= "od_bearings / 2 + 0.5 mm")
  dimension "d2218" distance P52 P53 = 1
  dimension "d2219" distance P25 L29 = 14
  dimension "d2221" distance L28 L32 = 1
  dimension "d2222" distance L38 P63 = 7 (= "od_bearings / 2 + 0.5 mm")
  dimension "d2223" distance L37 P64 = 6.7 (= "t_bearings + t_m4_washer * 2")
  dimension "d2224" distance P59 P65 = 31
  dimension "d2225" distance P64 L41 = 0.15
  dimension "d2226" distance P68 L43 = 0.15
  dimension "d2227" distance L45 P77 = 7 (= "od_bearings / 2 + 0.5 mm")
  dimension "d2229" distance P26 L44 = 7 (= "od_bearings / 2 + 0.5 mm")
  dimension "d2236" distance P84 P87 = 42.3
  dimension "d2237" diameter = 22.1
  dimension "d2238" distance P89 P92 = 31
  dimension "d2239" diameter = 3.5
  dimension "d2240" diameter = 7
  dimension "d2241" distance L5 P88 = 28
  dimension "d2244" distance P104 L68 = 7 (= "hw_m4hex_d")
  dimension "d2246" distance P112 L69 = 7 (= "hw_m4hex_d")
  dimension "d2247" diameter = 4.5
  dimension "d2248" distance P120 L75 = 7 (= "hw_m4hex_d")
  dimension "d2250" distance P128 L81 = 7 (= "hw_m4hex_d")
  dimension "d2252" distance P136 L87 = 7 (= "hw_m4hex_d")
  dimension "d2253" diameter = 4.5
  dimension "d2254" distance P144 L93 = 7 (= "hw_m4hex_d")
  dimension "d2256" distance L54 P131 = 5
  dimension "d2257" distance L52 L99 = 5
  dimension "d2258" distance L46 P132 = 6
  dimension "d2260" distance L31 P124 = 6
  dimension "d2261" distance L33 P116 = 5
  dimension "d2263" distance P85 L101 = 1
  dimension "d2264" distance P131 L109 = 4.5
  dimension "d2265" distance P86 L107 = 0.5
  dimension "d2266" distance P86 L104 = 0.5
  dimension "d2269" angle L111 L117 = 45
  dimension "d2270" distance P1 L116 = 20
  dimension "d2271" distance P168 P169 = 5
  dimension "d2272" distance P87 L112 = 0.5
  dimension "d2273" distance P147 L112 = 10
  dimension "d2279" distance = 1
  dimension "d2280" distance = 1 (= "d2279")
  dimension "d2281" distance = 7
  dimension "d2282" distance = 7 (= "d2281")
  dimension "d2286" distance P154 L105 = 0.5
  dimension "d2287" distance = 7 (= "hw_m4hex_d")
  dimension "d2295" distance = 7 (= "hw_m4hex_d")
  dimension "d2296" distance L118 P196 = 4
  dimension "d2297" diameter = 8.5
  dimension "d2349" distance = 5
  dimension "d2350" distance = 5 (= "d2349")
extrude "Extrude157" new body sketch "Top Plate" to an object
combine "Combine24"
offset_faces "OffsetFaces11" distance -0.1
extrude "Extrude158" cut sketch "Top Plate" to an object from offset 2
extrude "Extrude159" sketch "Top Plate" to an object bodies "YL Idler Cap", "YL Motor Plate"
extrude "Extrude166" sketch "Top Plate" to an object offset -2
fillet "Fillet70" radius 2
extrude "Extrude160" sketch "Top Plate" to an object offset -0.1
extrude "Extrude161" cut sketch "Top Plate" along normal blind 5.5
chamfer "Chamfer27" distance 1.7
extrude "Extrude162" add of existing geometry to an object
extrude "Extrude163" cut sketch "Profile" to an object
extrude "Extrude164" sketch "Top Plate" blind -25 from offset -14.5
extrude "Extrude165" cut sketch "Top Plate" to an object
chamfer "Chamfer28" distance 8
fillet "Fillet69" radius 0.5
chamfer "Chamfer29" distance 0.5
sketch "Limit Switch" plane through (10.5, 0, 0) normal (1, 0, 0) x axis (0, 1, 0)
  line L1 (42.4, -6.5) -> (42.4, -39.5)
  line L2 (50.9, -6.5) -> (42.4, -6.5)
  line L3 (50.9, -39.5) -> (50.9, -6.5)
  line L4 (42.4, -39.5) -> (50.9, -39.5)
  line L5 (35, -9.85) -> (35, 0)
  line L6 (20.25, -9.85) -> (35, -9.85)
  line L7 (20.25, -33.25) -> (20.25, -9.85)
  line L8 (-20.25, -33.25) -> (20.25, -33.25)
  line L9 (-20.25, 0) -> (-20.25, -33.25)
  line L10 (-22.99, 0) -> (-20.25, 0)
  line L11 (-22.99, 12) -> (-22.99, 0)
  line L12 (-42, 12) -> (-22.99, 12)
  line L13 (-42, -54.77) -> (-42, 12)
  line L14 (-24.4585, -54.77) -> (-42, -54.77)
  line L15 (-42, -55.77) -> (-24.4585, -55.77)
  line L16 (-42, -74.85) -> (-42, -55.77)
  line L17 (109, -74.85) -> (-42, -74.85)
  line L18 (109, -55.77) -> (109, -74.85)
  line L19 (91.4585, -55.77) -> (109, -55.77)
  line L20 (90.9585, -35.25) -> (90.9585, -55.27)
  line L21 (109, -35.25) -> (90.9585, -35.25)
  line L22 (109, 12) -> (109, -35.25)
  line L23 (95, 12) -> (109, 12)
  line L24 (95, 0) -> (95, 12)
  line L25 (35, 0) -> (95, 0)
  line L26 (95.9585, -71.81) -> (95.9585, -58.81)
  line L27 (91.4585, -72.31) -> (95.4585, -72.31)
  line L28 (90.9585, -58.81) -> (90.9585, -71.81)
  line L29 (95.4585, -58.31) -> (91.4585, -58.31)
  line L30 (-28.4585, -72.31) -> (-24.4585, -72.31)
  line L31 (-28.9585, -58.81) -> (-28.9585, -71.81)
  line L32 (-24.4585, -58.31) -> (-28.4585, -58.31)
  line L33 (-23.9585, -71.81) -> (-23.9585, -58.81)
  line L34 (106.0415, 5) -> (104.0207, 8.5)
  line L35 (104.0207, 1.5) -> (106.0415, 5)
  line L36 (99.9793, 1.5) -> (104.0207, 1.5)
  line L37 (97.9585, 5) -> (99.9793, 1.5)
  line L38 (99.9793, 8.5) -> (97.9585, 5)
  line L39 (104.0207, 8.5) -> (99.9793, 8.5)
  line L40 (-39.0415, 5) -> (-37.0207, 1.5)
  line L41 (-37.0207, 8.5) -> (-39.0415, 5)
  line L42 (-32.9793, 8.5) -> (-37.0207, 8.5)
  line L43 (-30.9585, 5) -> (-32.9793, 8.5)
  line L44 (-32.9793, 1.5) -> (-30.9585, 5)
  line L45 (-37.0207, 1.5) -> (-32.9793, 1.5)
  line L46 (97.9585, -67.85) -> (99.9793, -71.35)
  line L47 (99.9793, -64.35) -> (97.9585, -67.85)
  line L48 (104.0207, -64.35) -> (99.9793, -64.35)
  line L49 (106.0415, -67.85) -> (104.0207, -64.35)
  line L50 (104.0207, -71.35) -> (106.0415, -67.85)
  line L51 (99.9793, -71.35) -> (104.0207, -71.35)
  line L52 (-39.0415, -67.85) -> (-37.0207, -71.35)
  line L53 (-37.0207, -64.35) -> (-39.0415, -67.85)
  line L54 (-32.9793, -64.35) -> (-37.0207, -64.35)
  line L55 (-30.9585, -67.85) -> (-32.9793, -64.35)
  line L56 (-32.9793, -71.35) -> (-30.9585, -67.85)
  line L57 (-37.0207, -71.35) -> (-32.9793, -71.35)
  line L58 (90.9585, -35.25) -> (80.7585, -35.25)
  line L59 (90.9585, -55.05) -> (90.9585, -35.25)
  line L60 (80.7585, -55.05) -> (90.9585, -55.05)
  line L61 (80.7585, -35.25) -> (80.7585, -55.05)
  line L62 (83.2585, -49.85) -> (83.2585, -40.35)
  arc A1 centre (-24.4585, -55.27) radius 0.5 clockwise from (-24.4585, -54.77) to (-24.4585, -55.77)
  arc A2 centre (91.4585, -55.27) radius 0.5 clockwise from (91.4585, -55.77) to (90.9585, -55.27)
  arc A3 centre (95.4585, -71.81) radius 0.5 clockwise from (95.9585, -71.81) to (95.4585, -72.31)
  arc A4 centre (91.4585, -71.81) radius 0.5 clockwise from (91.4585, -72.31) to (90.9585, -71.81)
  arc A5 centre (91.4585, -58.81) radius 0.5 clockwise from (90.9585, -58.81) to (91.4585, -58.31)
  arc A6 centre (95.4585, -58.81) radius 0.5 clockwise from (95.4585, -58.31) to (95.9585, -58.81)
  arc A7 centre (-28.4585, -71.81) radius 0.5 clockwise from (-28.4585, -72.31) to (-28.9585, -71.81)
  arc A8 centre (-28.4585, -58.81) radius 0.5 clockwise from (-28.9585, -58.81) to (-28.4585, -58.31)
  arc A9 centre (-24.4585, -58.81) radius 0.5 clockwise from (-24.4585, -58.31) to (-23.9585, -58.81)
  arc A10 centre (-24.4585, -71.81) radius 0.5 clockwise from (-23.9585, -71.81) to (-24.4585, -72.31)
  circle C1 centre (83.2585, -40.35) radius 0.925
  circle C2 centre (83.2585, -49.85) radius 0.925
  point P84 (83.2585, -40.35)
  point P86 (83.2585, -40.35)
  point P85 (83.2585, -49.85)
  point P87 (83.2585, -49.85)
  point P27 (90.9585, -35.25)
  point P80 (80.7585, -35.25)
  point P83 (80.7585, -55.05)
  point P81 (90.9585, -35.25)
  horizontal L58
  vertical L59
  horizontal L60
  vertical L61
  vertical L62
  coincident P84 P86
  coincident P85 P87
  equal C1 C2
  coincident P27 L59
  coincident P27 L58
  dimension "d2364" distance P80 P83 = 19.8
  dimension "d2365" distance P80 P81 = 10.2
  dimension "d2366" distance P84 P85 = 9.5
  dimension "d2367" distance L58 P84 = 5.1
  dimension "d2368" distance L61 P84 = 2.5
  dimension "d2369" diameter C1 = 1.85
extrude "Extrude167" cut sketch "Limit Switch" profile of C1 C2 to an object
chamfer "Chamfer30" distance 0.5 distance 1.5
extrude "Extrude168" add of existing geometry blind 6
extrude "Extrude169" sketch "Profile" to an object
extrude "Extrude170" sketch "Profile" to an object
chamfer "Chamfer31" distance 3
sketch "Sketch39" plane through (0, 0, 0) normal (0, 0, 1) x axis (1, 0, 0)
  line L1 (29, 81) -> (29, 43)
  line L2 (29, 62) -> (0, 62)
  line L3 (30.1, 81.5) -> (28.2, 81.5)
  line L4 (30.1, 42.5) -> (30.1, 81.5)
  line L5 (28.2, 42.5) -> (30.1, 42.5)
  line L6 (28.2, 33.65) -> (28.2, 42.5)
  line L7 (34.1, 33.65) -> (28.2, 33.65)
  line L8 (34.1, 94.85) -> (34.1, 33.65)
  line L9 (28.2, 94.85) -> (34.1, 94.85)
  line L10 (28.2, 81.5) -> (28.2, 94.85)
  line L11 (31.7, 78.5) -> (30.1, 78.5)
  line L12 (31.7, 75) -> (31.7, 78.5)
  line L13 (30.1, 75) -> (31.7, 75)
  point P4 (29, 62)
  point P5 (0, 62)
  point P6 (0, 62)
  point P7 (29, 62)
  point P16 (28.2, 81.5)
  point P17 (28.1, 94.85)
  point P18 (28.1, 33.65)
  point P19 (30.1, 78.5)
  point P22 (30.1, 75)
  point P2 (29, 43)
  point P3 (29, 81)
  point P8 (28.1, 85.95)
  point P10 (30.1, 42.5)
  point P9 (30.1, 81.5)
  point P20 (31.7, 78.5)
  point P21 (31.7, 75)
  vertical L1
  midpoint L1 P4
  coincident P5 P6
  coincident P4 P7
  horizontal L2
  horizontal L3
  perpendicular L3 L4
  perpendicular L4 L5
  perpendicular L5 L6
  perpendicular L4 L7
  perpendicular L7 L8
  perpendicular L8 L9
  perpendicular L9 L10
  coincident L6 P16
  coincident L9 P17
  coincident L7 P18
  coincident L4 P19
  perpendicular L4 L11
  perpendicular L11 L12
  coincident L4 P22
  perpendicular L4 L13
  dimension "d2425" distance P2 P3 = 38
  dimension "d2426" distance L1 P8 = 0.9
  dimension "d2427" distance P8 L10 = 0.1
  dimension "d2429" distance P3 L3 = 0.5
  dimension "d2431" distance P2 L5 = 0.5
  dimension "d2433" distance P10 L8 = 4
  dimension "d2478" distance P9 P16 = 1.9
  dimension "d2504" distance P19 P20 = 1.6
  dimension "d2505" distance P20 P21 = 3.5
  dimension "d2506" distance P9 L11 = 3
extrude "Extrude171" new body sketch "Sketch39" profile of L3 L4 L5 L6 L7 L8 L9 L10 L11 L12 L13 to an object bodies "YL Cable Clip"
fillet "Fillet73" radius 1
sketch "Sketch40" plane through (34.1, 0, 0) normal (1, 0, 0) x axis (0, 1, 0)
  line L1 (33.65, 30.7) -> (94.85, 30.7)
  line L2 (33.65, 0) -> (33.65, 30.7)
  line L3 (94.85, 0) -> (33.65, 0)
  line L4 (94.85, 30.7) -> (94.85, 0)
  line L5 (37.65, 0) -> (37.65, 30.7)
  line L6 (90.85, 0) -> (90.85, 30.7)
  line L7 (90.85, 18.7) -> (37.65, 18.7)
  line L8 (37.65, 4) -> (90.85, 4)
  circle C1 centre (90.85, 18.7) radius 1.35
  circle C2 centre (90.85, 4) radius 1.35
  circle C3 centre (37.65, 4) radius 1.35
  circle C4 centre (90.85, 18.7) radius 1.625
  circle C5 centre (90.85, 4) radius 1.625
  circle C6 centre (37.65, 18.7) radius 1.35
  circle C7 centre (37.65, 4) radius 1.625
  circle C8 centre (37.65, 18.7) radius 1.625
  point P6 (37.65, 30.7)
  point P7 (37.65, 0)
  point P8 (90.85, 30.7)
  point P9 (90.85, 0)
  point P13 (90.85, 18.7)
  point P11 (90.85, 4)
  point P15 (37.65, 18.7)
  point P12 (37.65, 4)
  point P17 (37.65, 18.7)
  point P18 (37.65, 18.7)
  point P10 (90.85, 18.7)
  point P19 (90.85, 18.7)
  point P20 (90.85, 4)
  point P16 (37.65, 4)
  point P21 (37.65, 4)
  point P2 (94.85, 30.7)
  point P4 (33.65, 0)
  coincident L1 P6
  coincident L3 P7
  perpendicular L3 L5
  coincident L1 P8
  coincident L3 P9
  perpendicular L3 L6
  equal C1 C3
  equal C2 C3
  concentric C1 C4
  concentric C2 C5
  concentric C3 C7
  concentric C6 C8
  equal C1 C6
  equal C4 C5
  equal C4 C8
  equal C4 C7
  coincident L6 P13
  coincident L6 P11
  coincident L5 P15
  coincident L5 P12
  coincident P17 P18
  coincident P10 P19
  coincident P11 P20
  coincident P16 P21
  horizontal L8
  horizontal L7
  dimension "d2436" distance P2 L6 = 4
  dimension "d2437" distance P4 L5 = 4
  dimension "d2438" diameter C1 = 2.7
  dimension "d2439" diameter C4 = 3.25
  dimension "d2440" distance P8 L7 = 12
  dimension "d2441" distance P9 L8 = 4
extrude "Extrude172" cut sketch "Sketch40" profile of C1 C2 C3 C6 against normal blind 11
extrude "Extrude173" cut sketch "Sketch40" profile of C1 C2 C3 C4 C5 C6 C7 C8 to an object
chamfer "Chamfer32" distance 1.6
extrude "Extrude179" cut of existing geometry to an object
